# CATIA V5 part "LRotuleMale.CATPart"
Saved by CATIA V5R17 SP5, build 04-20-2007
Part number: RotuleMale
Publications: "Centre", "Facteur d'échelle"
Bounding box of the stored display mesh (mm): x -5 to 5, y -4.99 to 4.99, z -4.981 to 4.981
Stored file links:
  E:\Mes documents\03_Ressources pédagogiques\01_Catia\Buggy Dassault\SchemaCinematiqueFinal\LRotuleMale.CATPart
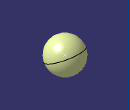
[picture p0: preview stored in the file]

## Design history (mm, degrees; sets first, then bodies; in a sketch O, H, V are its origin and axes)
External parameters (linked from other documents)
  `External.Facteur d'échelle` = 2
AxisSystem1: origin (0, 0, 0), X (1, 0, 0), Y (0, 1, 0), Z (0, 0, 1)
Body1 "RotuleMale" (main body)
  Circle1: type CtrRad, Start 0, End 180, Center vertex [YZ plane of AxisSystem1 | ZX plane of AxisSystem1 | XY plane of AxisSystem1], Support XY plane of AxisSystem1, Radius 5 {= 2.5mm*`External.Facteur d'échelle`}, FirstDirection (1, 0, 0)
  Revol1: Element1 Circle1, Line edge [XY plane of AxisSystem1 | ZX plane of AxisSystem1], Angle1 180
  Point1 "Centre": type Center, Curve Circle1
  Point2: (0, 0, 0), relative to vertex of Circle1, in AxisSystem1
